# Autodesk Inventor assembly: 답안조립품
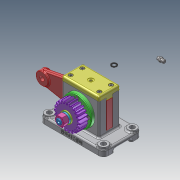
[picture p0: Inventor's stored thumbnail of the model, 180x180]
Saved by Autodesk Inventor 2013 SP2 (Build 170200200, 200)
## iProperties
Created: 2025-04
Part Number: 답안조립품
Document SubType Name: Assembly
Designer: i
Author: i
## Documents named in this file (15)
- C:\Users\i\Documents\Inventor\750404V1009\답안조립품.iam
- C:\Users\i\Documents\Inventor\750404V1009\본체.ipt
- C:\Users\i\Documents\Inventor\750404V1009\750404V1009\그리스 니플 M6x0.75.ipt
- C:\Users\i\Documents\Inventor\750404V1009\750404V1009\로드.ipt
- C:\Users\i\Documents\Inventor\750404V1009\750404V1009\스퍼기어.ipt
- C:\Users\i\Documents\Inventor\750404V1009\750404V1009\스프링와셔 M10.ipt
- C:\Users\i\Documents\Inventor\750404V1009\750404V1009\실링.ipt
- C:\Users\i\Documents\Inventor\750404V1009\750404V1009\앞커버.ipt
- C:\Users\i\Documents\Inventor\750404V1009\750404V1009\윗커버.ipt
- C:\Users\i\Documents\Inventor\750404V1009\750404V1009\육각 너트 M10.ipt
- C:\Users\i\Documents\Inventor\750404V1009\750404V1009\육각 소켓 머리 볼트 M4x10.ipt
- C:\Users\i\Documents\Inventor\750404V1009\750404V1009\편심축.ipt
- C:\Users\i\Documents\Inventor\750404V1009\750404V1009\평와셔 M10.ipt
- C:\Users\i\Documents\Inventor\750404V1009\750404V1009\평행키 4x4x10.ipt
- C:\Users\i\Documents\Inventor\750404V1009\750404V1009\플랜지 오일레스 부시.ipt
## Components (3 placed, 2 different names)
1. 그리스 니플 M6x0.75:1
2. 플랜지 오일레스 부시:1
3. 플랜지 오일레스 부시:2
